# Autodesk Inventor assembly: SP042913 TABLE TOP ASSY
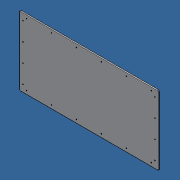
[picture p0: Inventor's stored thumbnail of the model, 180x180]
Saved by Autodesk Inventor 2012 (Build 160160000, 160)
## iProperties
Created: 2013-04
Part Number: SP042913 TABLE TOP ASSY
Document SubType Name: Assembly
Designer: Admin
Author: Admin
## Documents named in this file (4)
- C:\Andys Backup Data\ANDY'S INVENTOR\INVENTOR LIBRARIES\ASSEMBLY LIBRARY\45 SERIES\TABLES_CARTS\SP042913 MEDIUM DUTY TABLE\SP042913 TABLE TOP ASSY.iam
- C:\Andys Backup Data\ANDY'S INVENTOR\INVENTOR LIBRARIES\ASSEMBLY LIBRARY\45 SERIES\TABLES_CARTS\SP042913 MEDIUM DUTY TABLE\SP042913 TABLE TOP.ipt
- C:\Andys Backup Data\ANDY'S INVENTOR\INVENTOR LIBRARIES\PARTS LIBRARY\FASTENING ELEMENTS\SCREWS COUNTERSUNK\21.1566 M6X25 CSUNK.IPT
- C:\Andys Backup Data\ANDY'S INVENTOR\INVENTOR LIBRARIES\PARTS LIBRARY\FASTENING ELEMENTS\NUTS\21.1330_2 M6 SQUARE NUT POS FXG.ipt
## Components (41 placed, 3 different names)
1. SP042913 TABLE TOP:1 — Insert:1, Insert:2, Insert:3, Insert:4, Insert:5, Insert:6, Insert:7, Insert:8, Insert:9, Insert:10, Insert:11, Insert:12, Insert:13, Insert:14, Insert:15, Insert:16, Insert:17, Insert:18, Insert:19, Insert:20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
2. 21.1566 M6x25 C'SUNK:1 — Insert:1
3. 21.1566 M6x25 C'SUNK:2 — Insert:2
4. 21.1566 M6x25 C'SUNK:3 — Insert:3
5. 21.1566 M6x25 C'SUNK:4 — Insert:4
6. 21.1566 M6x25 C'SUNK:5 — Insert:5
7. 21.1566 M6x25 C'SUNK:6 — Insert:6
8. 21.1566 M6x25 C'SUNK:7 — Insert:7
9. 21.1566 M6x25 C'SUNK:8 — Insert:8
10. 21.1566 M6x25 C'SUNK:9 — Insert:9
11. 21.1566 M6x25 C'SUNK:10 — Insert:10
12. 21.1566 M6x25 C'SUNK:11 — Insert:11
13. 21.1566 M6x25 C'SUNK:12 — Insert:12
14. 21.1566 M6x25 C'SUNK:13 — Insert:13
15. 21.1566 M6x25 C'SUNK:14 — Insert:14
16. 21.1566 M6x25 C'SUNK:15 — Insert:15
17. 21.1566 M6x25 C'SUNK:16 — Insert:16
18. 21.1566 M6x25 C'SUNK:17 — Insert:17
19. 21.1566 M6x25 C'SUNK:18 — Insert:18
20. 21.1566 M6x25 C'SUNK:19 — Insert:19
21. 21.1566 M6x25 C'SUNK:20 — Insert:20
22. 21.1330_2 M6 SQUARE NUT POS FXG:1 — Insert:25, Angle:8
23. 21.1330_2 M6 SQUARE NUT POS FXG:2 — Insert:21, Angle:4
24. 21.1330_2 M6 SQUARE NUT POS FXG:3 — Insert:24, Angle:7
25. 21.1330_2 M6 SQUARE NUT POS FXG:4 — Insert:26, Angle:9
26. 21.1330_2 M6 SQUARE NUT POS FXG:5 — Insert:28, Angle:11
27. 21.1330_2 M6 SQUARE NUT POS FXG:6 — Insert:29, Angle:12
28. 21.1330_2 M6 SQUARE NUT POS FXG:7 — Insert:27, Angle:10
29. 21.1330_2 M6 SQUARE NUT POS FXG:8 — Insert:40, Angle:3
30. 21.1330_2 M6 SQUARE NUT POS FXG:9 — Insert:31, Angle:14
31. 21.1330_2 M6 SQUARE NUT POS FXG:10 — Insert:30, Angle:13
32. 21.1330_2 M6 SQUARE NUT POS FXG:11 — Insert:32, Angle:15
33. 21.1330_2 M6 SQUARE NUT POS FXG:12 — Insert:33, Angle:16
34. 21.1330_2 M6 SQUARE NUT POS FXG:13 — Insert:34, Angle:17
35. 21.1330_2 M6 SQUARE NUT POS FXG:14 — Insert:35, Angle:18
36. 21.1330_2 M6 SQUARE NUT POS FXG:15 — Insert:36, Angle:19
37. 21.1330_2 M6 SQUARE NUT POS FXG:16 — Insert:37, Angle:20
38. 21.1330_2 M6 SQUARE NUT POS FXG:17 — Insert:23, Angle:6
39. 21.1330_2 M6 SQUARE NUT POS FXG:18 — Insert:39, Angle:2
40. 21.1330_2 M6 SQUARE NUT POS FXG:19 — Insert:38, Angle:1, Angle:21
41. 21.1330_2 M6 SQUARE NUT POS FXG:20 — Insert:22, Angle:5
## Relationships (61: Insert 40, Angle 21)
- Insert:1: SP042913 TABLE TOP:1 ↔ 21.1566 M6x25 C'SUNK:1
- Insert:2: SP042913 TABLE TOP:1 ↔ 21.1566 M6x25 C'SUNK:2
- Insert:3: SP042913 TABLE TOP:1 ↔ 21.1566 M6x25 C'SUNK:3
- Insert:4: SP042913 TABLE TOP:1 ↔ 21.1566 M6x25 C'SUNK:4
- Insert:5: SP042913 TABLE TOP:1 ↔ 21.1566 M6x25 C'SUNK:5
- Insert:6: SP042913 TABLE TOP:1 ↔ 21.1566 M6x25 C'SUNK:6
- Insert:7: SP042913 TABLE TOP:1 ↔ 21.1566 M6x25 C'SUNK:7
- Insert:8: SP042913 TABLE TOP:1 ↔ 21.1566 M6x25 C'SUNK:8
- Insert:9: SP042913 TABLE TOP:1 ↔ 21.1566 M6x25 C'SUNK:9
- Insert:10: SP042913 TABLE TOP:1 ↔ 21.1566 M6x25 C'SUNK:10
- Insert:11: SP042913 TABLE TOP:1 ↔ 21.1566 M6x25 C'SUNK:11
- Insert:12: SP042913 TABLE TOP:1 ↔ 21.1566 M6x25 C'SUNK:12
- Insert:13: SP042913 TABLE TOP:1 ↔ 21.1566 M6x25 C'SUNK:13
- Insert:14: SP042913 TABLE TOP:1 ↔ 21.1566 M6x25 C'SUNK:14
- Insert:15: SP042913 TABLE TOP:1 ↔ 21.1566 M6x25 C'SUNK:15
- Insert:16: SP042913 TABLE TOP:1 ↔ 21.1566 M6x25 C'SUNK:16
- Insert:17: SP042913 TABLE TOP:1 ↔ 21.1566 M6x25 C'SUNK:17
- Insert:18: SP042913 TABLE TOP:1 ↔ 21.1566 M6x25 C'SUNK:18
- Insert:19: SP042913 TABLE TOP:1 ↔ 21.1566 M6x25 C'SUNK:19
- Insert:20: SP042913 TABLE TOP:1 ↔ 21.1566 M6x25 C'SUNK:20
- Insert:21: SP042913 TABLE TOP:1 ↔ 21.1330_2 M6 SQUARE NUT POS FXG:2
- Insert:22: SP042913 TABLE TOP:1 ↔ 21.1330_2 M6 SQUARE NUT POS FXG:20
- Insert:23: SP042913 TABLE TOP:1 ↔ 21.1330_2 M6 SQUARE NUT POS FXG:17
- Insert:24: SP042913 TABLE TOP:1 ↔ 21.1330_2 M6 SQUARE NUT POS FXG:3
- Insert:25: SP042913 TABLE TOP:1 ↔ 21.1330_2 M6 SQUARE NUT POS FXG:1
- Insert:26: SP042913 TABLE TOP:1 ↔ 21.1330_2 M6 SQUARE NUT POS FXG:4
- Insert:27: SP042913 TABLE TOP:1 ↔ 21.1330_2 M6 SQUARE NUT POS FXG:7
- Insert:28: SP042913 TABLE TOP:1 ↔ 21.1330_2 M6 SQUARE NUT POS FXG:5
- Insert:29: SP042913 TABLE TOP:1 ↔ 21.1330_2 M6 SQUARE NUT POS FXG:6
- Insert:30: SP042913 TABLE TOP:1 ↔ 21.1330_2 M6 SQUARE NUT POS FXG:10
- Insert:31: SP042913 TABLE TOP:1 ↔ 21.1330_2 M6 SQUARE NUT POS FXG:9
- Insert:32: SP042913 TABLE TOP:1 ↔ 21.1330_2 M6 SQUARE NUT POS FXG:11
- Insert:33: SP042913 TABLE TOP:1 ↔ 21.1330_2 M6 SQUARE NUT POS FXG:12
- Insert:34: SP042913 TABLE TOP:1 ↔ 21.1330_2 M6 SQUARE NUT POS FXG:13
- Insert:35: SP042913 TABLE TOP:1 ↔ 21.1330_2 M6 SQUARE NUT POS FXG:14
- Insert:36: SP042913 TABLE TOP:1 ↔ 21.1330_2 M6 SQUARE NUT POS FXG:15
- Insert:37: SP042913 TABLE TOP:1 ↔ 21.1330_2 M6 SQUARE NUT POS FXG:16
- Insert:38: SP042913 TABLE TOP:1 ↔ 21.1330_2 M6 SQUARE NUT POS FXG:19
- Insert:39: SP042913 TABLE TOP:1 ↔ 21.1330_2 M6 SQUARE NUT POS FXG:18
- Insert:40: SP042913 TABLE TOP:1 ↔ 21.1330_2 M6 SQUARE NUT POS FXG:8
- Angle:1: SP042913 TABLE TOP:1 ↔ 21.1330_2 M6 SQUARE NUT POS FXG:19
- Angle:2: SP042913 TABLE TOP:1 ↔ 21.1330_2 M6 SQUARE NUT POS FXG:18
- Angle:3: SP042913 TABLE TOP:1 ↔ 21.1330_2 M6 SQUARE NUT POS FXG:8
- Angle:4: SP042913 TABLE TOP:1 ↔ 21.1330_2 M6 SQUARE NUT POS FXG:2
- Angle:5: SP042913 TABLE TOP:1 ↔ 21.1330_2 M6 SQUARE NUT POS FXG:20
- Angle:6: SP042913 TABLE TOP:1 ↔ 21.1330_2 M6 SQUARE NUT POS FXG:17
- Angle:7: SP042913 TABLE TOP:1 ↔ 21.1330_2 M6 SQUARE NUT POS FXG:3
- Angle:8: SP042913 TABLE TOP:1 ↔ 21.1330_2 M6 SQUARE NUT POS FXG:1
- Angle:9: SP042913 TABLE TOP:1 ↔ 21.1330_2 M6 SQUARE NUT POS FXG:4
- Angle:10: SP042913 TABLE TOP:1 ↔ 21.1330_2 M6 SQUARE NUT POS FXG:7
- Angle:11: SP042913 TABLE TOP:1 ↔ 21.1330_2 M6 SQUARE NUT POS FXG:5
- Angle:12: SP042913 TABLE TOP:1 ↔ 21.1330_2 M6 SQUARE NUT POS FXG:6
- Angle:13: SP042913 TABLE TOP:1 ↔ 21.1330_2 M6 SQUARE NUT POS FXG:10
- Angle:14: SP042913 TABLE TOP:1 ↔ 21.1330_2 M6 SQUARE NUT POS FXG:9
- Angle:15: SP042913 TABLE TOP:1 ↔ 21.1330_2 M6 SQUARE NUT POS FXG:11
- Angle:16: SP042913 TABLE TOP:1 ↔ 21.1330_2 M6 SQUARE NUT POS FXG:12
- Angle:17: SP042913 TABLE TOP:1 ↔ 21.1330_2 M6 SQUARE NUT POS FXG:13
- Angle:18: SP042913 TABLE TOP:1 ↔ 21.1330_2 M6 SQUARE NUT POS FXG:14
- Angle:19: SP042913 TABLE TOP:1 ↔ 21.1330_2 M6 SQUARE NUT POS FXG:15
- Angle:20: SP042913 TABLE TOP:1 ↔ 21.1330_2 M6 SQUARE NUT POS FXG:16
- Angle:21: SP042913 TABLE TOP:1 ↔ 21.1330_2 M6 SQUARE NUT POS FXG:19
